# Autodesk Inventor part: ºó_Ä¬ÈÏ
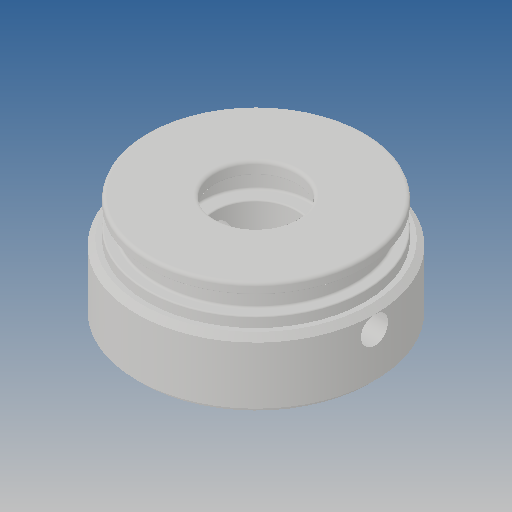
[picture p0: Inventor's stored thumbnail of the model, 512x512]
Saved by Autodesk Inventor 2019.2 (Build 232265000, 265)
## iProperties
Created: 2011-12
Part Number: ºó_Ä¬ÈÏ
Material: Ogólny
Document SubType Name: Modeling
Designer: CADENGINEERING4
Density: 1 g/cm^3
Appearance: Domyślna
Author: CADENGINEERING4
Revision Number: ÈÎºÎ
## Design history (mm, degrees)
feature "NONE"
node "Bryła1"
